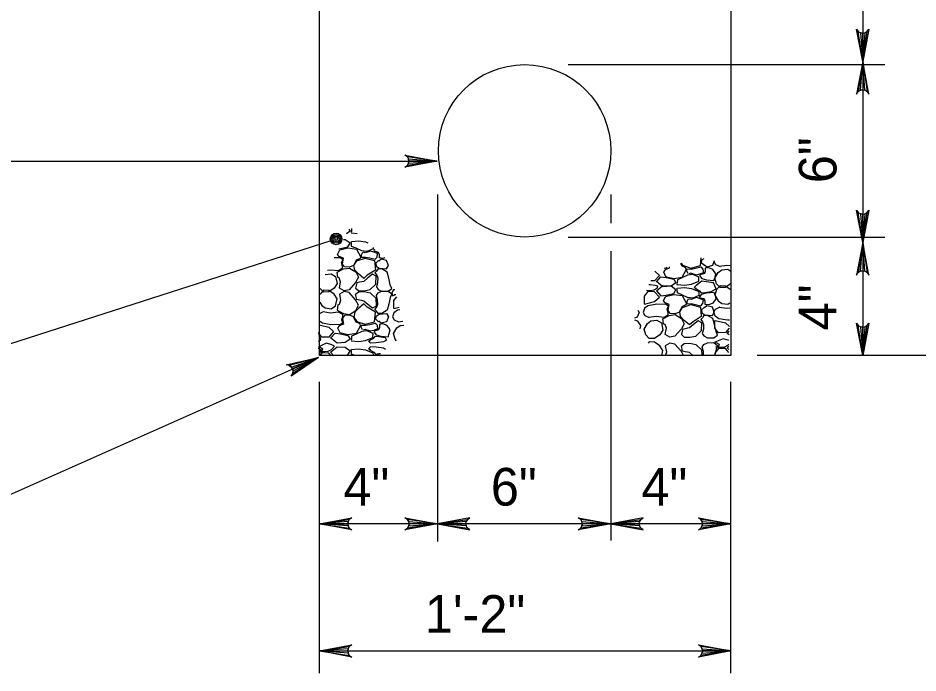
# Model space of a CAD drawing. Extents: x -0.97 to 5.98, y -2.63 to 7.27.
# Drawn here: x 3.389 to 4.822, y 4.115 to 5.158 of the extents above; entities that cross this region are included whole.
import ezdxf

# ---------------------------------------------------------------- set-up
doc = ezdxf.new("R2010")
doc.units = 0
for name, color, linetype in [('DETL-DIMS', 7, 'Continuous'), ('DETL-LINE', 7, 'Continuous'), ('DETL-NOTE', 7, 'Continuous'), ('DETL-PATT', 7, 'Continuous')]:
    doc.layers.add(name, color=color, linetype=linetype)

msp = doc.modelspace()

# ---------------------------------------------------------------- linework, layer by layer
at = {"layer": 'DETL-DIMS'}
for p, q in [((4.7339, 5.8562), (4.7339, 4.6209)), ((4.265, 5.084), (4.7693, 5.084)), ((3.3702, 4.9303), (4.0534, 4.9303)), ((4.0567, 4.8773), (4.0567, 4.3247)), ((4.3326, 4.8773), (4.3326, 4.8317)), ((3.8868, 4.8034), (3.36, 4.6342)), ((4.265, 4.8094), (4.7693, 4.8094)), ((4.3326, 4.7872), (4.3326, 4.3265)), ((3.2591, 4.3478), (3.8673, 4.6179)), ((5.0535, 4.6209), (4.5658, 4.6209)), ((3.8687, 4.1154), (3.8687, 4.5792)), ((4.5242, 4.1154), (4.5242, 4.5792)), ((4.5242, 4.3529), (3.8687, 4.3529)), ((3.8687, 4.1505), (4.5242, 4.1505))]:
    msp.add_line(p, q, dxfattribs=at)
for points in [[(4.7339, 5.0889), (4.7242, 5.1406), (4.7269, 5.1367), (4.7304, 5.1346), (4.7339, 5.134), (4.7373, 5.1346), (4.7408, 5.1367), (4.7436, 5.1406), (4.7339, 5.0889), (4.7408, 5.1367), (4.7373, 5.1346), (4.7339, 5.0889), (4.7339, 5.134), (4.7304, 5.1346), (4.7339, 5.0889), (4.7269, 5.1367)], [(4.7339, 5.0889), (4.7242, 5.0371), (4.7269, 5.0411), (4.7304, 5.0431), (4.7339, 5.0437), (4.7373, 5.0431), (4.7408, 5.0411), (4.7436, 5.0371), (4.7339, 5.0889), (4.7408, 5.0411), (4.7373, 5.0431), (4.7339, 5.0889), (4.7339, 5.0437), (4.7304, 5.0431), (4.7339, 5.0889), (4.7269, 5.0411)], [(4.0565, 4.9303), (4.0048, 4.9206), (4.0088, 4.9233), (4.0108, 4.9268), (4.0114, 4.9303), (4.0108, 4.9338), (4.0088, 4.9372), (4.0048, 4.94), (4.0565, 4.9303), (4.0088, 4.9372), (4.0108, 4.9338), (4.0565, 4.9303), (4.0114, 4.9303), (4.0108, 4.9268), (4.0565, 4.9303), (4.0088, 4.9233)], [(4.7339, 4.8007), (4.7242, 4.8525), (4.7269, 4.8485), (4.7304, 4.8465), (4.7339, 4.8459), (4.7373, 4.8465), (4.7408, 4.8485), (4.7436, 4.8525), (4.7339, 4.8007), (4.7408, 4.8485), (4.7373, 4.8465), (4.7339, 4.8007), (4.7339, 4.8459), (4.7304, 4.8465), (4.7339, 4.8007), (4.7269, 4.8485)], [(4.7339, 4.8007), (4.7242, 4.7489), (4.7269, 4.7529), (4.7304, 4.755), (4.7339, 4.7556), (4.7373, 4.755), (4.7408, 4.7529), (4.7436, 4.7489), (4.7339, 4.8007), (4.7408, 4.7529), (4.7373, 4.755), (4.7339, 4.8007), (4.7339, 4.7556), (4.7304, 4.755), (4.7339, 4.8007), (4.7269, 4.7529)], [(4.7339, 4.6209), (4.7242, 4.6726), (4.7269, 4.6687), (4.7304, 4.6666), (4.7339, 4.666), (4.7373, 4.6666), (4.7408, 4.6687), (4.7436, 4.6726), (4.7339, 4.6209), (4.7408, 4.6687), (4.7373, 4.6666), (4.7339, 4.6209), (4.7339, 4.666), (4.7304, 4.6666), (4.7339, 4.6209), (4.7269, 4.6687)], [(3.8673, 4.6179), (3.8239, 4.588), (3.8264, 4.5922), (3.8269, 4.5962), (3.826, 4.5996), (3.8241, 4.6025), (3.8208, 4.6049), (3.816, 4.6058), (3.8673, 4.6179), (3.8208, 4.6049), (3.8241, 4.6025), (3.8673, 4.6179), (3.826, 4.5996), (3.8269, 4.5962), (3.8673, 4.6179), (3.8264, 4.5922)], [(3.8687, 4.3529), (3.9204, 4.3626), (3.9164, 4.3599), (3.9144, 4.3564), (3.9138, 4.3529), (3.9144, 4.3495), (3.9164, 4.346), (3.9204, 4.3432), (3.8687, 4.3529), (3.9164, 4.346), (3.9144, 4.3495), (3.8687, 4.3529), (3.9138, 4.3529), (3.9144, 4.3564), (3.8687, 4.3529), (3.9164, 4.3599)], [(4.0567, 4.3529), (4.0049, 4.3432), (4.0089, 4.346), (4.011, 4.3495), (4.0116, 4.3529), (4.011, 4.3564), (4.0089, 4.3599), (4.0049, 4.3626), (4.0567, 4.3529), (4.0089, 4.3599), (4.011, 4.3564), (4.0567, 4.3529), (4.0116, 4.3529), (4.011, 4.3495), (4.0567, 4.3529), (4.0089, 4.346)], [(4.0567, 4.3529), (4.1085, 4.3432), (4.1045, 4.346), (4.1025, 4.3495), (4.1019, 4.3529), (4.1025, 4.3564), (4.1045, 4.3599), (4.1085, 4.3626), (4.0567, 4.3529), (4.1045, 4.3599), (4.1025, 4.3564), (4.0567, 4.3529), (4.1019, 4.3529), (4.1025, 4.3495), (4.0567, 4.3529), (4.1045, 4.346)], [(4.3326, 4.3529), (4.2809, 4.3432), (4.2849, 4.346), (4.2869, 4.3495), (4.2875, 4.3529), (4.2869, 4.3564), (4.2849, 4.3599), (4.2809, 4.3626), (4.3326, 4.3529), (4.2849, 4.3599), (4.2869, 4.3564), (4.3326, 4.3529), (4.2875, 4.3529), (4.2869, 4.3495), (4.3326, 4.3529), (4.2849, 4.346)], [(4.3326, 4.3529), (4.3844, 4.3432), (4.3804, 4.346), (4.3784, 4.3495), (4.3778, 4.3529), (4.3784, 4.3564), (4.3804, 4.3599), (4.3844, 4.3626), (4.3326, 4.3529), (4.3804, 4.3599), (4.3784, 4.3564), (4.3326, 4.3529), (4.3778, 4.3529), (4.3784, 4.3495), (4.3326, 4.3529), (4.3804, 4.346)], [(4.5242, 4.3529), (4.4724, 4.3432), (4.4764, 4.346), (4.4784, 4.3495), (4.479, 4.3529), (4.4784, 4.3564), (4.4764, 4.3599), (4.4724, 4.3626), (4.5242, 4.3529), (4.4764, 4.3599), (4.4784, 4.3564), (4.5242, 4.3529), (4.479, 4.3529), (4.4784, 4.3495), (4.5242, 4.3529), (4.4764, 4.346)], [(3.8687, 4.1505), (3.9204, 4.1602), (3.9164, 4.1574), (3.9144, 4.1539), (3.9138, 4.1505), (3.9144, 4.147), (3.9164, 4.1435), (3.9204, 4.1407), (3.8687, 4.1505), (3.9164, 4.1435), (3.9144, 4.147), (3.8687, 4.1505), (3.9138, 4.1505), (3.9144, 4.1539), (3.8687, 4.1505), (3.9164, 4.1574)], [(4.5242, 4.1505), (4.4724, 4.1407), (4.4764, 4.1435), (4.4784, 4.147), (4.479, 4.1505), (4.4784, 4.1539), (4.4764, 4.1574), (4.4724, 4.1602), (4.5242, 4.1505), (4.4764, 4.1574), (4.4784, 4.1539), (4.5242, 4.1505), (4.479, 4.1505), (4.4784, 4.147), (4.5242, 4.1505), (4.4764, 4.1435)]]:
    msp.add_lwpolyline(points, dxfattribs=at)
for radius in [0.00926, 0.00694, 0.00463, 0.00231]:
    msp.add_circle((3.8954, 4.8064), radius, dxfattribs=at)
at = {"layer": 'DETL-LINE'}
for p, q in [((3.8687, 4.6209), (3.8687, 5.8562)), ((4.5242, 5.8562), (4.5242, 4.6209)), ((4.5242, 4.6209), (3.8687, 4.6209))]:
    msp.add_line(p, q, dxfattribs=at)
msp.add_circle((4.1956, 4.9467), 0.1373, dxfattribs=at)
at = {"layer": 'DETL-PATT'}
for points in [[(3.9158, 4.8218), (3.9177, 4.8187), (3.9121, 4.8147)], [(3.92, 4.8231), (3.9197, 4.8187), (3.9194, 4.8172), (3.9197, 4.8158)], [(3.9197, 4.8161), (3.929, 4.8151)], [(3.8995, 4.7908), (3.9023, 4.7911), (3.9142, 4.7937), (3.9177, 4.7995), (3.9099, 4.805), (3.9071, 4.8052)], [(3.9542, 4.793), (3.9543, 4.7905), (3.9444, 4.7862), (3.9363, 4.7874), (3.9273, 4.7917), (3.92, 4.7946), (3.9197, 4.7995), (3.9194, 4.801), (3.9197, 4.8024)], [(3.9197, 4.8021), (3.9311, 4.8033), (3.9424, 4.8016), (3.9461, 4.8001)], [(3.9238, 4.7642), (3.9162, 4.7613), (3.9087, 4.7618), (3.9055, 4.7665), (3.9069, 4.776), (3.9003, 4.7787), (3.8977, 4.7818), (3.9011, 4.7891), (3.9142, 4.7923), (3.9279, 4.7903), (3.9342, 4.7787), (3.9334, 4.7755), (3.9273, 4.7726), (3.9232, 4.7644)], [(3.9374, 4.7847), (3.9351, 4.7807), (3.9351, 4.7772), (3.9421, 4.7775), (3.9491, 4.7763), (3.9575, 4.774), (3.9607, 4.7775), (3.9615, 4.7833), (3.9554, 4.7856), (3.9502, 4.7871), (3.9415, 4.7842), (3.9383, 4.7853)], [(3.9554, 4.7879), (3.9572, 4.7903)], [(3.9728, 4.7766), (3.97, 4.7755), (3.9642, 4.7763), (3.9642, 4.7813), (3.963, 4.7847), (3.9563, 4.7868), (3.9557, 4.7876)], [(3.8816, 4.7568), (3.8863, 4.7575), (3.8988, 4.756), (3.9055, 4.7598), (3.9055, 4.7627), (3.904, 4.7688), (3.9058, 4.7734), (3.9023, 4.7763), (3.892, 4.7765)], [(3.9309, 4.7507), (3.9252, 4.7569), (3.9238, 4.7644), (3.9281, 4.7714), (3.9415, 4.776), (3.9566, 4.772), (3.9581, 4.7569), (3.945, 4.7485), (3.9395, 4.7436), (3.9308, 4.7508)], [(3.963, 4.772), (3.9586, 4.7679), (3.9589, 4.763), (3.9639, 4.7598), (3.9758, 4.7586), (3.9787, 4.7642), (3.9758, 4.772), (3.9671, 4.7743), (3.9633, 4.7711)], [(4.445, 4.7676), (4.4469, 4.7646), (4.4603, 4.76), (4.4754, 4.764), (4.4766, 4.7764)], [(4.4818, 4.764), (4.4774, 4.7681), (4.4777, 4.773), (4.4813, 4.7753)], [(3.8979, 4.7454), (3.8968, 4.7534), (3.9069, 4.7589), (3.9165, 4.7601), (3.9267, 4.754), (3.9308, 4.7456), (3.9264, 4.7372), (3.916, 4.7256), (3.9081, 4.7238), (3.9009, 4.7282), (3.9026, 4.7383), (3.9003, 4.7444), (3.8974, 4.7456)], [(3.9615, 4.7369), (3.9595, 4.7302), (3.9624, 4.7262), (3.9679, 4.7233), (3.9778, 4.723), (3.9839, 4.7273), (3.9816, 4.7334), (3.9793, 4.7441), (3.9764, 4.7537), (3.9682, 4.7586), (3.9621, 4.7586), (3.9598, 4.7549), (3.9572, 4.7523), (3.9601, 4.7488), (3.9618, 4.7441), (3.9615, 4.7372)], [(4.4255, 4.7619), (4.4257, 4.76), (4.4191, 4.7573), (4.4165, 4.7542), (4.4199, 4.7469), (4.433, 4.7437), (4.4467, 4.7457), (4.453, 4.7573), (4.4522, 4.7605), (4.4461, 4.7634), (4.4441, 4.7674)], [(4.4228, 4.7611), (4.4211, 4.7597), (4.4179, 4.7596)], [(4.4562, 4.7513), (4.4539, 4.7553), (4.4539, 4.7588), (4.4609, 4.7585), (4.4679, 4.7597), (4.4763, 4.762), (4.4795, 4.7585), (4.4803, 4.7527), (4.4742, 4.7504), (4.469, 4.7489), (4.4603, 4.7518), (4.4571, 4.7507)], [(4.4742, 4.7481), (4.4777, 4.7434), (4.4853, 4.7411), (4.4969, 4.7402), (4.4989, 4.7455), (4.5001, 4.751), (4.4954, 4.7579), (4.4888, 4.7605), (4.483, 4.7597), (4.483, 4.7547), (4.4818, 4.7513), (4.4751, 4.7492), (4.4745, 4.7484)], [(4.4975, 4.7718), (4.4946, 4.764), (4.4859, 4.7617), (4.4821, 4.7649)], [(4.4972, 4.7718), (4.4969, 4.7707), (4.4995, 4.766), (4.5068, 4.7626)], [(4.5061, 4.7629), (4.5178, 4.7646), (4.5239, 4.7639)], [(3.878, 4.75), (3.8875, 4.7511), (3.8945, 4.7468), (3.8968, 4.7354), (3.8921, 4.7279), (3.8837, 4.7221), (3.8753, 4.7218), (3.87, 4.7277)], [(3.9325, 4.7375), (3.9284, 4.7366), (3.9264, 4.7282), (3.9308, 4.7244), (3.9401, 4.7238), (3.9496, 4.7259), (3.9584, 4.7346), (3.9592, 4.747), (3.9531, 4.7502), (3.9459, 4.7444), (3.9395, 4.7389), (3.9363, 4.7383), (3.9325, 4.7375)], [(4.403, 4.7549), (4.4101, 4.7484), (4.4025, 4.7397), (4.3963, 4.7395)], [(4.4054, 4.7382), (4.4124, 4.746), (4.4211, 4.7449), (4.433, 4.7423), (4.4365, 4.7365), (4.4287, 4.731), (4.4156, 4.7301), (4.4054, 4.7385)], [(4.4385, 4.7339), (4.4499, 4.7327), (4.4612, 4.7344), (4.4728, 4.7391), (4.4731, 4.7455), (4.4632, 4.7498), (4.4551, 4.7486), (4.4461, 4.7443), (4.4388, 4.7414), (4.4385, 4.7365), (4.4382, 4.735), (4.4385, 4.7336)], [(4.5232, 4.7347), (4.5152, 4.7292), (4.5068, 4.7289), (4.5013, 4.735), (4.4986, 4.744), (4.5039, 4.753)], [(4.5039, 4.753), (4.5094, 4.7571), (4.519, 4.7582), (4.5237, 4.7552)], [(4.3899, 4.725), (4.3961, 4.7246), (4.4016, 4.7252), (4.4066, 4.7278), (4.4075, 4.731), (4.4037, 4.7324), (4.3955, 4.7336), (4.3936, 4.7333)], [(4.4054, 4.7237), (4.4124, 4.7159), (4.4211, 4.717), (4.433, 4.7196), (4.4365, 4.7254), (4.4287, 4.731), (4.4156, 4.7318), (4.4054, 4.7234)], [(4.467, 4.7278), (4.4742, 4.7237), (4.4769, 4.7205), (4.4824, 4.7214), (4.4925, 4.7228), (4.5008, 4.7272), (4.4962, 4.7365), (4.4776, 4.7394), (4.4687, 4.7321), (4.4655, 4.7289), (4.4681, 4.7283), (4.4681, 4.7272)], [(4.523, 4.7262), (4.5152, 4.7315), (4.5068, 4.7318), (4.5013, 4.7257), (4.4986, 4.7167), (4.5039, 4.7078)], [(3.8724, 4.7006), (3.8779, 4.6966), (3.8875, 4.6954), (3.8945, 4.6998), (3.8968, 4.7111), (3.8921, 4.7186), (3.8837, 4.7244), (3.8753, 4.7247), (3.8698, 4.7186), (3.8697, 4.7183)], [(3.8979, 4.7011), (3.8968, 4.6931), (3.9069, 4.6876), (3.9165, 4.6864), (3.9267, 4.6925), (3.9308, 4.7009), (3.9264, 4.7093), (3.916, 4.7209), (3.9081, 4.7227), (3.9009, 4.7183), (3.9026, 4.7082), (3.9003, 4.7021), (3.8974, 4.7009)], [(3.9325, 4.7091), (3.9284, 4.7099), (3.9264, 4.7183), (3.9308, 4.7221), (3.9401, 4.7227), (3.9496, 4.7207), (3.9584, 4.712), (3.9592, 4.6995), (3.9531, 4.6963), (3.9459, 4.7021), (3.9395, 4.7076), (3.9363, 4.7082), (3.9325, 4.7091)], [(3.9615, 4.7096), (3.9595, 4.7163), (3.9624, 4.7204), (3.9679, 4.7233), (3.9778, 4.7236), (3.9839, 4.7192), (3.9816, 4.7131), (3.9793, 4.7024), (3.9764, 4.6928), (3.9682, 4.6879), (3.9621, 4.6879), (3.9598, 4.6917), (3.9572, 4.6943), (3.9601, 4.6977), (3.9618, 4.7024), (3.9615, 4.7093)], [(3.9888, 4.7255), (3.9868, 4.7253), (3.9839, 4.7207), (3.9851, 4.7157), (3.9877, 4.7169), (3.9883, 4.718)], [(3.988, 4.718), (3.9907, 4.7179)], [(4.3865, 4.7028), (4.4025, 4.7066), (4.4101, 4.7136), (4.4025, 4.7223), (4.3915, 4.7225), (4.386, 4.7153), (4.3857, 4.7028)], [(4.4426, 4.6901), (4.435, 4.6872), (4.4275, 4.6877), (4.4243, 4.6924), (4.4257, 4.702), (4.4191, 4.7046), (4.4165, 4.7078), (4.4199, 4.715), (4.433, 4.7182), (4.4467, 4.7162), (4.453, 4.7046), (4.4522, 4.7014), (4.4461, 4.6985), (4.442, 4.6904)], [(4.4385, 4.7281), (4.4499, 4.7292), (4.4612, 4.7275), (4.4728, 4.7228), (4.4731, 4.7165), (4.4632, 4.7121), (4.4551, 4.7133), (4.4461, 4.7176), (4.4388, 4.7205), (4.4385, 4.7254), (4.4382, 4.7269), (4.4385, 4.7283)], [(4.4742, 4.7138), (4.4777, 4.7185), (4.4853, 4.7208), (4.4969, 4.7217), (4.4989, 4.7165), (4.5001, 4.7109), (4.4954, 4.704), (4.4888, 4.7014), (4.483, 4.7022), (4.483, 4.7072), (4.4818, 4.7107), (4.4751, 4.7127), (4.4745, 4.7136)], [(3.8693, 4.706), (3.8724, 4.7006)], [(3.9309, 4.6959), (3.9252, 4.6896), (3.9238, 4.6821), (3.9281, 4.6751), (3.9415, 4.6705), (3.9566, 4.6745), (3.9581, 4.6896), (3.945, 4.698), (3.9395, 4.703), (3.9308, 4.6957)], [(3.9916, 4.7145), (3.9868, 4.7082), (3.9865, 4.6957)], [(4.3934, 4.6817), (4.4051, 4.6834), (4.4176, 4.6819), (4.4243, 4.6857), (4.4243, 4.6886), (4.4228, 4.6947), (4.4246, 4.6993), (4.4211, 4.7022), (4.406, 4.7025), (4.3923, 4.7002), (4.3863, 4.6962), (4.3842, 4.6895), (4.3868, 4.6848), (4.3941, 4.6814)], [(4.4497, 4.6766), (4.444, 4.6828), (4.4426, 4.6904), (4.4469, 4.6973), (4.4603, 4.702), (4.4754, 4.6979), (4.4769, 4.6828), (4.4638, 4.6744), (4.4583, 4.6695), (4.4496, 4.6767)], [(4.4562, 4.7107), (4.4539, 4.7066), (4.4539, 4.7031), (4.4609, 4.7034), (4.4679, 4.7022), (4.4763, 4.6999), (4.4795, 4.7034), (4.4803, 4.7092), (4.4742, 4.7115), (4.469, 4.713), (4.4603, 4.7101), (4.4571, 4.7112)], [(4.5039, 4.7078), (4.5094, 4.7037), (4.519, 4.7025), (4.5225, 4.7047)], [(3.8746, 4.6907), (3.8863, 4.689), (3.8988, 4.6905), (3.9055, 4.6867), (3.9055, 4.6838), (3.904, 4.6777), (3.9058, 4.6731), (3.9023, 4.6702), (3.8872, 4.6699), (3.8736, 4.6722), (3.8683, 4.6757)], [(3.8687, 4.6879), (3.8753, 4.6911)], [(3.963, 4.6745), (3.9586, 4.6786), (3.9589, 4.6835), (3.9639, 4.6867), (3.9758, 4.6879), (3.9787, 4.6824), (3.9758, 4.6745), (3.9671, 4.6722), (3.9633, 4.6754)], [(3.9968, 4.6937), (3.9932, 4.6931), (3.9871, 4.689), (3.9851, 4.6824), (3.9877, 4.6777), (3.9949, 4.6743)], [(3.9874, 4.6957), (3.9958, 4.6977)], [(4.376, 4.693), (4.3778, 4.6895), (4.3749, 4.6817), (4.3705, 4.6805)], [(4.4818, 4.6979), (4.4774, 4.6938), (4.4777, 4.6889), (4.4827, 4.6857), (4.4946, 4.6846), (4.4975, 4.6901), (4.4946, 4.6979), (4.4859, 4.7002), (4.4821, 4.697)], [(4.5218, 4.6771), (4.5187, 4.677), (4.505, 4.6793), (4.4989, 4.6834), (4.4969, 4.6901), (4.4995, 4.6947), (4.5068, 4.6982)], [(4.5061, 4.6978), (4.5178, 4.6962), (4.5223, 4.6967)], [(3.9238, 4.6824), (3.9162, 4.6853), (3.9087, 4.6847), (3.9055, 4.6801), (3.9069, 4.6705), (3.9003, 4.6679), (3.8977, 4.6647), (3.9011, 4.6574), (3.9142, 4.6542), (3.9279, 4.6563), (3.9342, 4.6679), (3.9334, 4.6711), (3.9273, 4.674), (3.9232, 4.6821)], [(3.9374, 4.6618), (3.9351, 4.6658), (3.9351, 4.6693), (3.9421, 4.669), (3.9491, 4.6702), (3.9575, 4.6725), (3.9607, 4.669), (3.9615, 4.6632), (3.9554, 4.6609), (3.9502, 4.6595), (3.9415, 4.6624), (3.9383, 4.6612)], [(3.9942, 4.6746), (4.0014, 4.6756)], [(4.3793, 4.6634), (4.3804, 4.6686), (4.3758, 4.6756), (4.3712, 4.6773)], [(4.3912, 4.6718), (4.3967, 4.6759), (4.4063, 4.677), (4.4133, 4.6727), (4.4156, 4.6614), (4.4109, 4.6538), (4.4025, 4.648), (4.3941, 4.6477), (4.3886, 4.6538), (4.386, 4.6628), (4.3912, 4.6718)], [(4.4167, 4.6713), (4.4156, 4.6793), (4.4257, 4.6848), (4.4353, 4.686), (4.4455, 4.6799), (4.4496, 4.6715), (4.4452, 4.6631), (4.4347, 4.6515), (4.4269, 4.6498), (4.4196, 4.6541), (4.4214, 4.6643), (4.4191, 4.6703), (4.4162, 4.6715)], [(4.4513, 4.6634), (4.4472, 4.6625), (4.4452, 4.6541), (4.4496, 4.6503), (4.4589, 4.6498), (4.4684, 4.6518), (4.4772, 4.6605), (4.478, 4.673), (4.4719, 4.6761), (4.4647, 4.6703), (4.4583, 4.6648), (4.4551, 4.6643), (4.4513, 4.6634)], [(4.4803, 4.6628), (4.4783, 4.6561), (4.4812, 4.6521), (4.4867, 4.6492), (4.4966, 4.6489), (4.5027, 4.6532), (4.5004, 4.6593), (4.4981, 4.6701), (4.4952, 4.6796), (4.487, 4.6846), (4.4809, 4.6846), (4.4786, 4.6808), (4.476, 4.6782), (4.4789, 4.6747), (4.4806, 4.6701), (4.4803, 4.6631)], [(4.5215, 4.6645), (4.5152, 4.6573), (4.5042, 4.657), (4.4986, 4.6643), (4.4984, 4.6767)], [(4.4992, 4.6767), (4.5152, 4.673), (4.5216, 4.6671)], [(3.8682, 4.6695), (3.8837, 4.6658), (3.8913, 4.6589), (3.8837, 4.6502), (3.8727, 4.6499), (3.8677, 4.6564)], [(3.9197, 4.6444), (3.9311, 4.6432), (3.9424, 4.645), (3.954, 4.6496), (3.9543, 4.656), (3.9444, 4.6603), (3.9363, 4.6592), (3.9273, 4.6548), (3.92, 4.6519), (3.9197, 4.647), (3.9194, 4.6455), (3.9197, 4.6441)], [(3.9554, 4.6586), (3.9589, 4.654), (3.9665, 4.6516), (3.9781, 4.6508), (3.9801, 4.656), (3.9813, 4.6615), (3.9766, 4.6685), (3.97, 4.6711), (3.9642, 4.6702), (3.9642, 4.6653), (3.963, 4.6618), (3.9563, 4.6598), (3.9557, 4.6589)], [(3.9917, 4.6442), (3.9894, 4.6467), (3.9868, 4.6557), (3.992, 4.6647)], [(3.992, 4.6647), (3.9976, 4.6687), (4.003, 4.6694)], [(4.5181, 4.6558), (4.5214, 4.6595)], [(3.8673, 4.6434), (3.8712, 4.6461), (3.8689, 4.6522), (3.8678, 4.6574)], [(3.8866, 4.6487), (3.8936, 4.6566), (3.9023, 4.6554), (3.9142, 4.6528), (3.9177, 4.647), (3.9099, 4.6415), (3.8968, 4.6406), (3.8866, 4.649)], [(3.9482, 4.6447), (3.9554, 4.6487), (3.9581, 4.6519), (3.9636, 4.6511), (3.9737, 4.6496), (3.9758, 4.6455), (3.9708, 4.6424), (3.9592, 4.6409), (3.9499, 4.6403), (3.9467, 4.6435), (3.9494, 4.6441), (3.9494, 4.6453)], [(4.521, 4.6445), (4.5198, 4.6451), (4.5117, 4.6474), (4.4986, 4.6419), (4.5018, 4.6411), (4.5053, 4.6387), (4.5036, 4.6335), (4.5001, 4.6347)], [(4.5212, 4.6536), (4.5181, 4.6561)], [(3.867, 4.6329), (3.8712, 4.6299), (3.8689, 4.6238), (3.8684, 4.6213)], [(3.8721, 4.627), (3.8773, 4.627), (3.8828, 4.6276), (3.8878, 4.6302), (3.893, 4.6357), (3.8884, 4.638), (3.8802, 4.6403), (3.8672, 4.6348), (3.8704, 4.6339), (3.8738, 4.6316), (3.8721, 4.6264), (3.8686, 4.6276)], [(3.9121, 4.6216), (3.9142, 4.6221), (3.9177, 4.6279), (3.9099, 4.6334), (3.8968, 4.6342), (3.8866, 4.6258)], [(3.9256, 4.6207), (3.92, 4.6229), (3.9197, 4.6279), (3.9194, 4.6293), (3.9197, 4.6308)], [(3.9197, 4.6305), (3.9311, 4.6316), (3.9424, 4.6299), (3.954, 4.6252), (3.9542, 4.6218)], [(3.974, 4.6304), (3.9708, 4.6325), (3.9592, 4.6339), (3.9499, 4.6345), (3.9467, 4.6313), (3.9494, 4.6308), (3.9494, 4.6296)], [(3.9482, 4.6302), (3.9554, 4.6261), (3.9581, 4.6229), (3.9636, 4.6238), (3.966, 4.6241)], [(4.4138, 4.6204), (4.4156, 4.6289), (4.4109, 4.6364), (4.4025, 4.6422), (4.3941, 4.6425), (4.3925, 4.6407)], [(4.4483, 4.6211), (4.4452, 4.6271), (4.4347, 4.6387), (4.4269, 4.6405), (4.4196, 4.6361), (4.4214, 4.626), (4.4193, 4.6205)], [(4.4513, 4.6268), (4.4472, 4.6277), (4.4452, 4.6361), (4.4496, 4.6399), (4.4589, 4.6405), (4.4684, 4.6384), (4.4772, 4.6297), (4.4777, 4.6217)], [(4.4803, 4.6274), (4.4783, 4.6341), (4.4812, 4.6382), (4.4867, 4.6411), (4.4966, 4.6413), (4.5027, 4.637), (4.5004, 4.6309), (4.4985, 4.6221)], [(4.5205, 4.6256), (4.5152, 4.6318), (4.5042, 4.6321), (4.4986, 4.6248), (4.4986, 4.6221)], [(4.5036, 4.6341), (4.5088, 4.6341), (4.5143, 4.6347), (4.5193, 4.6373), (4.5209, 4.639)], [(4.5208, 4.6351), (4.5181, 4.6329)], [(4.5181, 4.6332), (4.5206, 4.6304)], [(3.8873, 4.6206), (3.8837, 4.6247), (3.8727, 4.625), (3.8699, 4.6212)], [(3.8866, 4.6261), (3.8917, 4.6204)], [(3.9617, 4.6217), (3.9637, 4.6223)], [(4.4629, 4.6214), (4.4583, 4.6254), (4.4551, 4.626), (4.4513, 4.6268)], [(4.4806, 4.6217), (4.4803, 4.6271)]]:
    msp.add_lwpolyline(points, dxfattribs=at)

# ---------------------------------------------------------------- texts
at = {"layer": 'DETL-NOTE'}
for s, p in [('6"', (4.6922, 4.8952)), ('4"', (4.6922, 4.6609))]:
    msp.add_text(s, height=0.06, rotation=90, dxfattribs=at).set_placement(p)
for s, p in [('4"', (3.907, 4.3819)), ('6"', (4.1418, 4.3819)), ('4"', (4.3816, 4.3819)), ('1\'-2"', (4.0368, 4.1794))]:
    msp.add_text(s, height=0.06, dxfattribs=at).set_placement(p)

doc.saveas('drawing.dxf')
